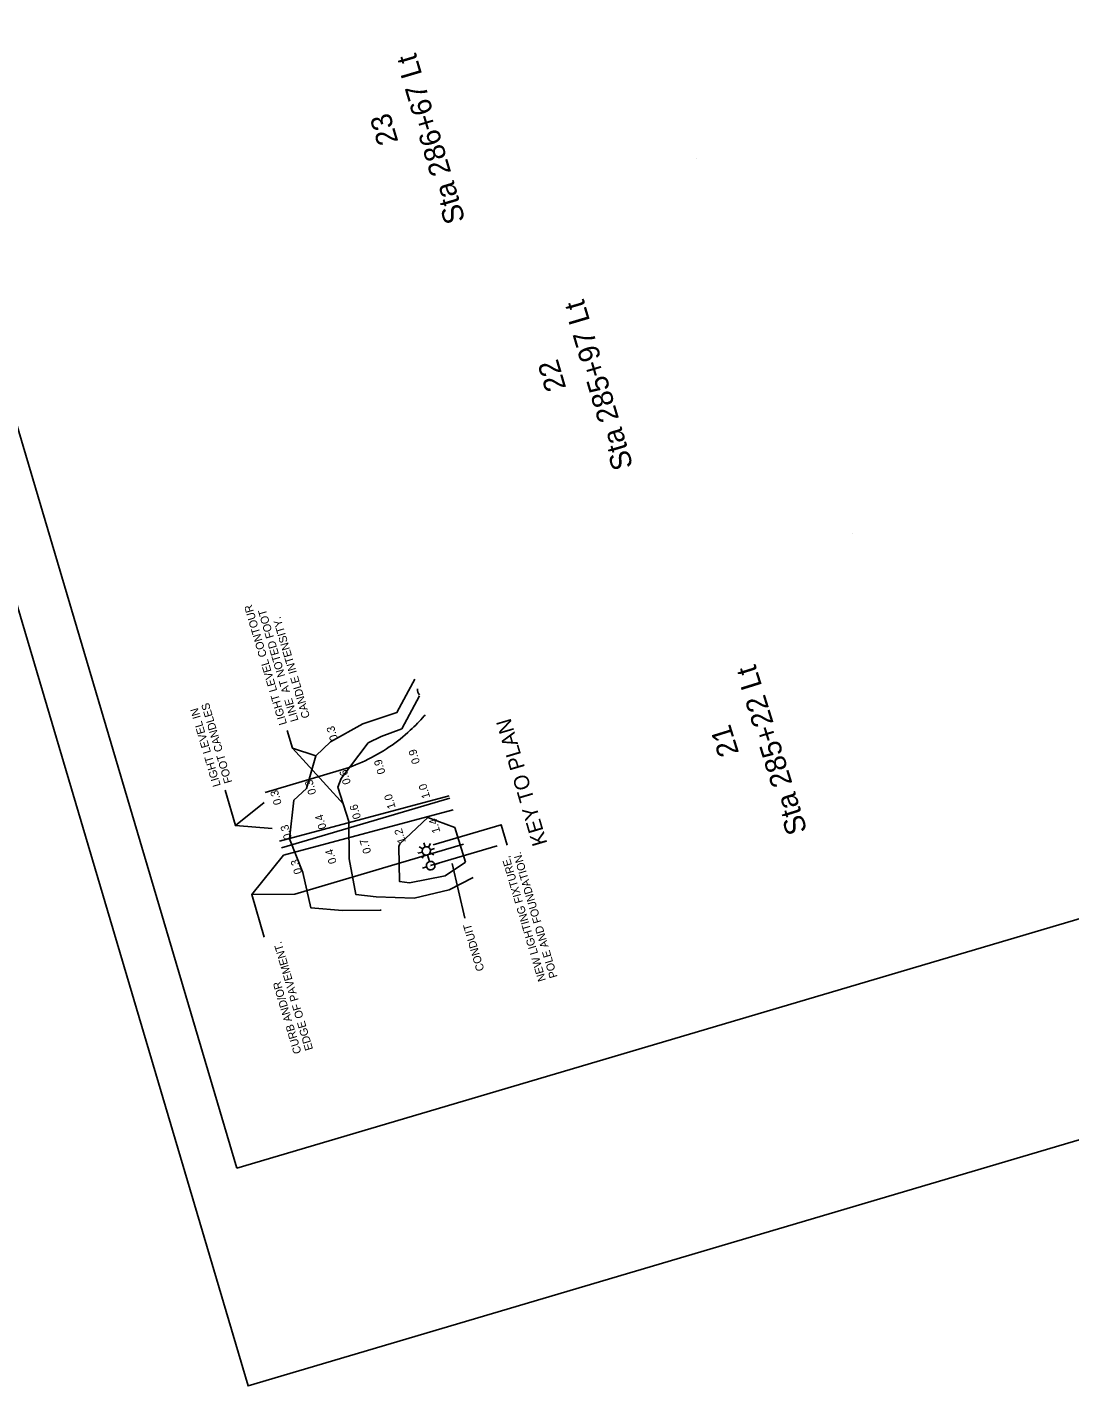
# Model space of a CAD drawing. Extents: x 1111051 to 1111820, y 617600 to 618625.
# Drawn here: x 1111250.2 to 1111449.3, y 617653.7 to 617913 of the extents above; entities that cross this region are included whole.
import ezdxf

# ---------------------------------------------------------------- set-up
doc = ezdxf.new("R2010")
doc.units = 0
for name, color, linetype in [('ANNOTATION', 7, 'Continuous'), ('BORDER', 7, 'Continuous'), ('D_Lighting_Text', 7, 'Continuous'), ('D_Utilities_Pole_StreetLight', 7, 'Continuous'), ('Default', 7, 'Continuous'), ('Liting Text', 7, 'Continuous'), ('PLOT BOUNDARY', 7, 'Continuous')]:
    doc.layers.add(name, color=color, linetype=linetype)

msp = doc.modelspace()

# ---------------------------------------------------------------- linework, layer by layer
at = {"layer": 'ANNOTATION'}
for p, q in [((1111300.85, 617775.41), (1111310.58, 617764.69)), ((1111309.8, 617771.1), (1111295.63, 617766.91)), ((1111289.97, 617760.61), (1111295.45, 617765.01)), ((1111330.78, 617766.28), (1111298.38, 617757.6)), ((1111330.9, 617765.86), (1111298.75, 617756.35)), ((1111299.16, 617754.96), (1111331.55, 617763.63)), ((1111301.34, 617747.54), (1111333.49, 617757.06)), ((1111327.52, 617756.2), (1111327.5, 617756.24)), ((1111324.88, 617755.42), (1111324.86, 617755.46)), ((1111325.65, 617752.78), (1111325.64, 617752.82)), ((1111326.93, 617752.71), (1111326.93, 617752.71)), ((1111327.03, 617752.38), (1111327.03, 617752.38)), ((1111327.26, 617752.81), (1111327.26, 617752.81)), ((1111327.36, 617752.48), (1111327.36, 617752.48)), ((1111333.79, 617742.9), (1111331.34, 617753.35)), ((1111293.08, 617747.44), (1111301.34, 617747.54))]:
    msp.add_line(p, q, dxfattribs=at)
for points in [[(1111317.8, 617744.45), (1111317.59, 617744.43), (1111310.43, 617744.37), (1111304.37, 617744.89), (1111302.83, 617751.62), (1111300.3, 617758.05), (1111301.13, 617765.48), (1111303.56, 617767.66), (1111305.35, 617773.91), (1111308.1, 617776.6), (1111314.27, 617780.03), (1111320.8, 617782.22), (1111323, 617786.31), (1111324.21, 617788.54)], [(1111335.36, 617750.72), (1111330.78, 617748.37), (1111324.08, 617746.75), (1111316.83, 617747), (1111312.97, 617747.44), (1111311.7, 617754.25), (1111311.63, 617761.4), (1111309.54, 617767.97), (1111310.16, 617769.62), (1111315.33, 617776.42), (1111317.8, 617777.59), (1111321.73, 617779.07), (1111325.14, 617785.39)], [(1111299.85, 617778.78), (1111300.85, 617775.41), (1111305.35, 617773.91)], [(1111287.98, 617767.35), (1111289.97, 617760.61), (1111296.97, 617760.02)], [(1111333.9, 617753.63), (1111331.85, 617760.21), (1111326.71, 617762.18), (1111321.38, 617757.11), (1111321.17, 617756.64), (1111321.31, 617749.91), (1111323.22, 617749.69), (1111330.01, 617750.99), (1111333.9, 617753.63)], [(1111341.83, 617756.86), (1111340.68, 617760.76), (1111327.72, 617756.93)], [(1111295.48, 617739.28), (1111293.08, 617747.44), (1111299.16, 617754.96)]]:
    msp.add_lwpolyline(points, dxfattribs=at)
for centre, major_axis, start_param, end_param in [((1111326.11, 617786.49), (0.44, 1.3), 1.737973, 2.633498), ((1111300.06, 617804.12), (11.08, 32.6), 4.213502, 4.323837), ((1111300.06, 617804.12), (11.08, 32.6), 4.323837, 4.333024), ((1111300.06, 617804.12), (11.08, 32.6), 4.064294, 4.213502), ((1111300.06, 617804.12), (11.08, 32.6), 3.756531, 4.064294)]:
    msp.add_ellipse(centre, major_axis=major_axis, ratio=0.998974, start_param=start_param, end_param=end_param, dxfattribs=at)
at = {"layer": 'BORDER'}
for p, q in [((1111063.13, 618462.3), (1111290.21, 617695.21)), ((1111290.21, 617695.21), (1111793.62, 617844.23))]:
    msp.add_line(p, q, dxfattribs=at)
at = {"layer": 'D_Utilities_Pole_StreetLight'}
for p, q in [((1111325.72, 617756.16), (1111325.02, 617756.54)), ((1111326.2, 617756.54), (1111325.97, 617757.31)), ((1111326.81, 617756.47), (1111327.19, 617757.18)), ((1111327.19, 617756), (1111327.96, 617756.22)), ((1111325.65, 617755.55), (1111324.88, 617755.32)), ((1111326.03, 617755.07), (1111325.65, 617754.37)), ((1111327.01, 617753.74), (1111326.64, 617755)), ((1111327.12, 617755.39), (1111327.82, 617755)), ((1111326.45, 617752.73), (1111325.66, 617752.5)), ((1111328.02, 617753.19), (1111328.81, 617753.42))]:
    msp.add_line(p, q, dxfattribs=at)
for centre, major_axis in [((1111326.42, 617755.77), (-0.258, -0.758)), ((1111327.24, 617752.96), (0.264, 0.776))]:
    msp.add_ellipse(centre, major_axis=major_axis, ratio=0.998974, dxfattribs=at)
at = {"layer": 'Default'}
for p, q in [((1111377.99, 617888.04), (1111377.99, 617888.04)), ((1111407.73, 617816.45), (1111407.73, 617816.45))]:
    msp.add_line(p, q, dxfattribs=at)
msp.add_lwpolyline([(1111292.39, 617653.65), (1111051.12, 618468.69), (1111578.49, 618624.81), (1111819.77, 617809.77)], close=True, dxfattribs=at)
at = {"layer": 'Liting Text'}
msp.add_line((1111327.24, 617752.96), (1111339.95, 617756.72), dxfattribs=at)
at = {"layer": 'PLOT BOUNDARY'}
msp.add_lwpolyline([(1111819.77, 617809.77), (1111578.49, 618624.81), (1111051.12, 618468.69), (1111292.39, 617653.65)], close=True, dxfattribs=at)

# ---------------------------------------------------------------- texts
at = {"layer": 'ANNOTATION'}
for s, height, p in [('LIGHT LEVEL CONTOUR', 1.528, (1111299.82, 617780.04)), ('LINE  AT NOTED FOOT', 1.528, (1111302.02, 617780.69)), ('CANDLE INTENSITY.', 1.528, (1111304.22, 617781.34)), ('LIGHT LEVEL IN', 1.528, (1111287.18, 617768.27)), ('FOOT CANDLES', 1.528, (1111289.37, 617768.92)), ('0.3', 1.528, (1111309.57, 617777.03)), ('KEY TO PLAN', 2.8603, (1111349.54, 617757.21)), ('0.9', 1.528, (1111325.23, 617772.61)), ('0.9', 1.528, (1111318.63, 617770.66)), ('0.3', 1.528, (1111305.43, 617766.75)), ('0.6', 1.528, (1111312.03, 617768.7)), ('0.3', 1.528, (1111298.83, 617764.8)), ('1.0', 1.528, (1111320.57, 617764.05)), ('1.0', 1.528, (1111327.17, 617766.01)), ('0.6', 1.528, (1111313.97, 617762.1)), ('0.4', 1.528, (1111307.37, 617760.15)), ('1.4', 1.528, (1111329.12, 617759.4)), ('0.3', 1.528, (1111300.77, 617758.19)), ('1.2', 1.528, (1111322.52, 617757.45)), ('0.7', 1.528, (1111315.92, 617755.49)), ('0.3', 1.528, (1111302.72, 617751.59)), ('0.4', 1.528, (1111309.32, 617753.54)), ('NEW LIGHTING FIXTURE,', 1.528, (1111349.28, 617731.09)), ('POLE AND FOUNDATION.', 1.528, (1111351.48, 617731.74)), ('CONDUIT', 1.528, (1111337.51, 617733.06)), ('EDGE OF PAVEMENT.', 1.528, (1111304.8, 617717.92)), ('CURB AND/OR', 1.528, (1111302.6, 617717.27))]:
    msp.add_text(s, height=height, rotation=106.4315, dxfattribs=at).set_placement(p)
at = {"layer": 'D_Lighting_Text'}
for s, rotation, p in [('Sta 286+67 Lt', 106.4903, (1111333.89, 617876.16)), ('23', 106.4903, (1111321.1, 617891.18)), ('Sta 285+97 Lt', 106.4903, (1111365.94, 617829.15)), ('22', 106.4903, (1111353.15, 617844.17)), ('Sta 285+22 Lt', 107.3101, (1111399.19, 617759.57)), ('21', 107.3101, (1111386.16, 617774.47))]:
    msp.add_text(s, height=4, rotation=rotation, dxfattribs=at).set_placement(p)

doc.saveas('drawing.dxf')
